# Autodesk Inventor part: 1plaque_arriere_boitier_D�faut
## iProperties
Created: 2011-01
Part Number: 1plaque_arriere_boitier_D�faut
Document SubType Name: Modeling
Designer: eric
Density: 1 g/cm^3
Mass: 5.02583 g
Surface Area: 38.973 cm^2
Volume: 5.02583 cm^3
Author: eric
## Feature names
1. Base1
